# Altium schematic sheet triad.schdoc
size 594 x 419 mm; Symbol: Drawing-Symbol_A4; @Project Name: Inverted_MAML_6x6; @Page Count: 1; @Update Date: 2026-06-20; @Create Date: 2026-06-20; @Schematic Name: Schematic1; @Page No: 1; @Page Name: P1; Company: EasyEDA.com; Version: V1.0; Page Size: A4; Device: Drawing-Symbol_A4; @Create Time: 09:40:42; @Update Time: 09:40:42; Border: 1; Width: 2338; Height: 1652; Region Start: 1; X Region Count: 6; Y Region Count: 4; Blade Width: 10; Title Block Position: 3
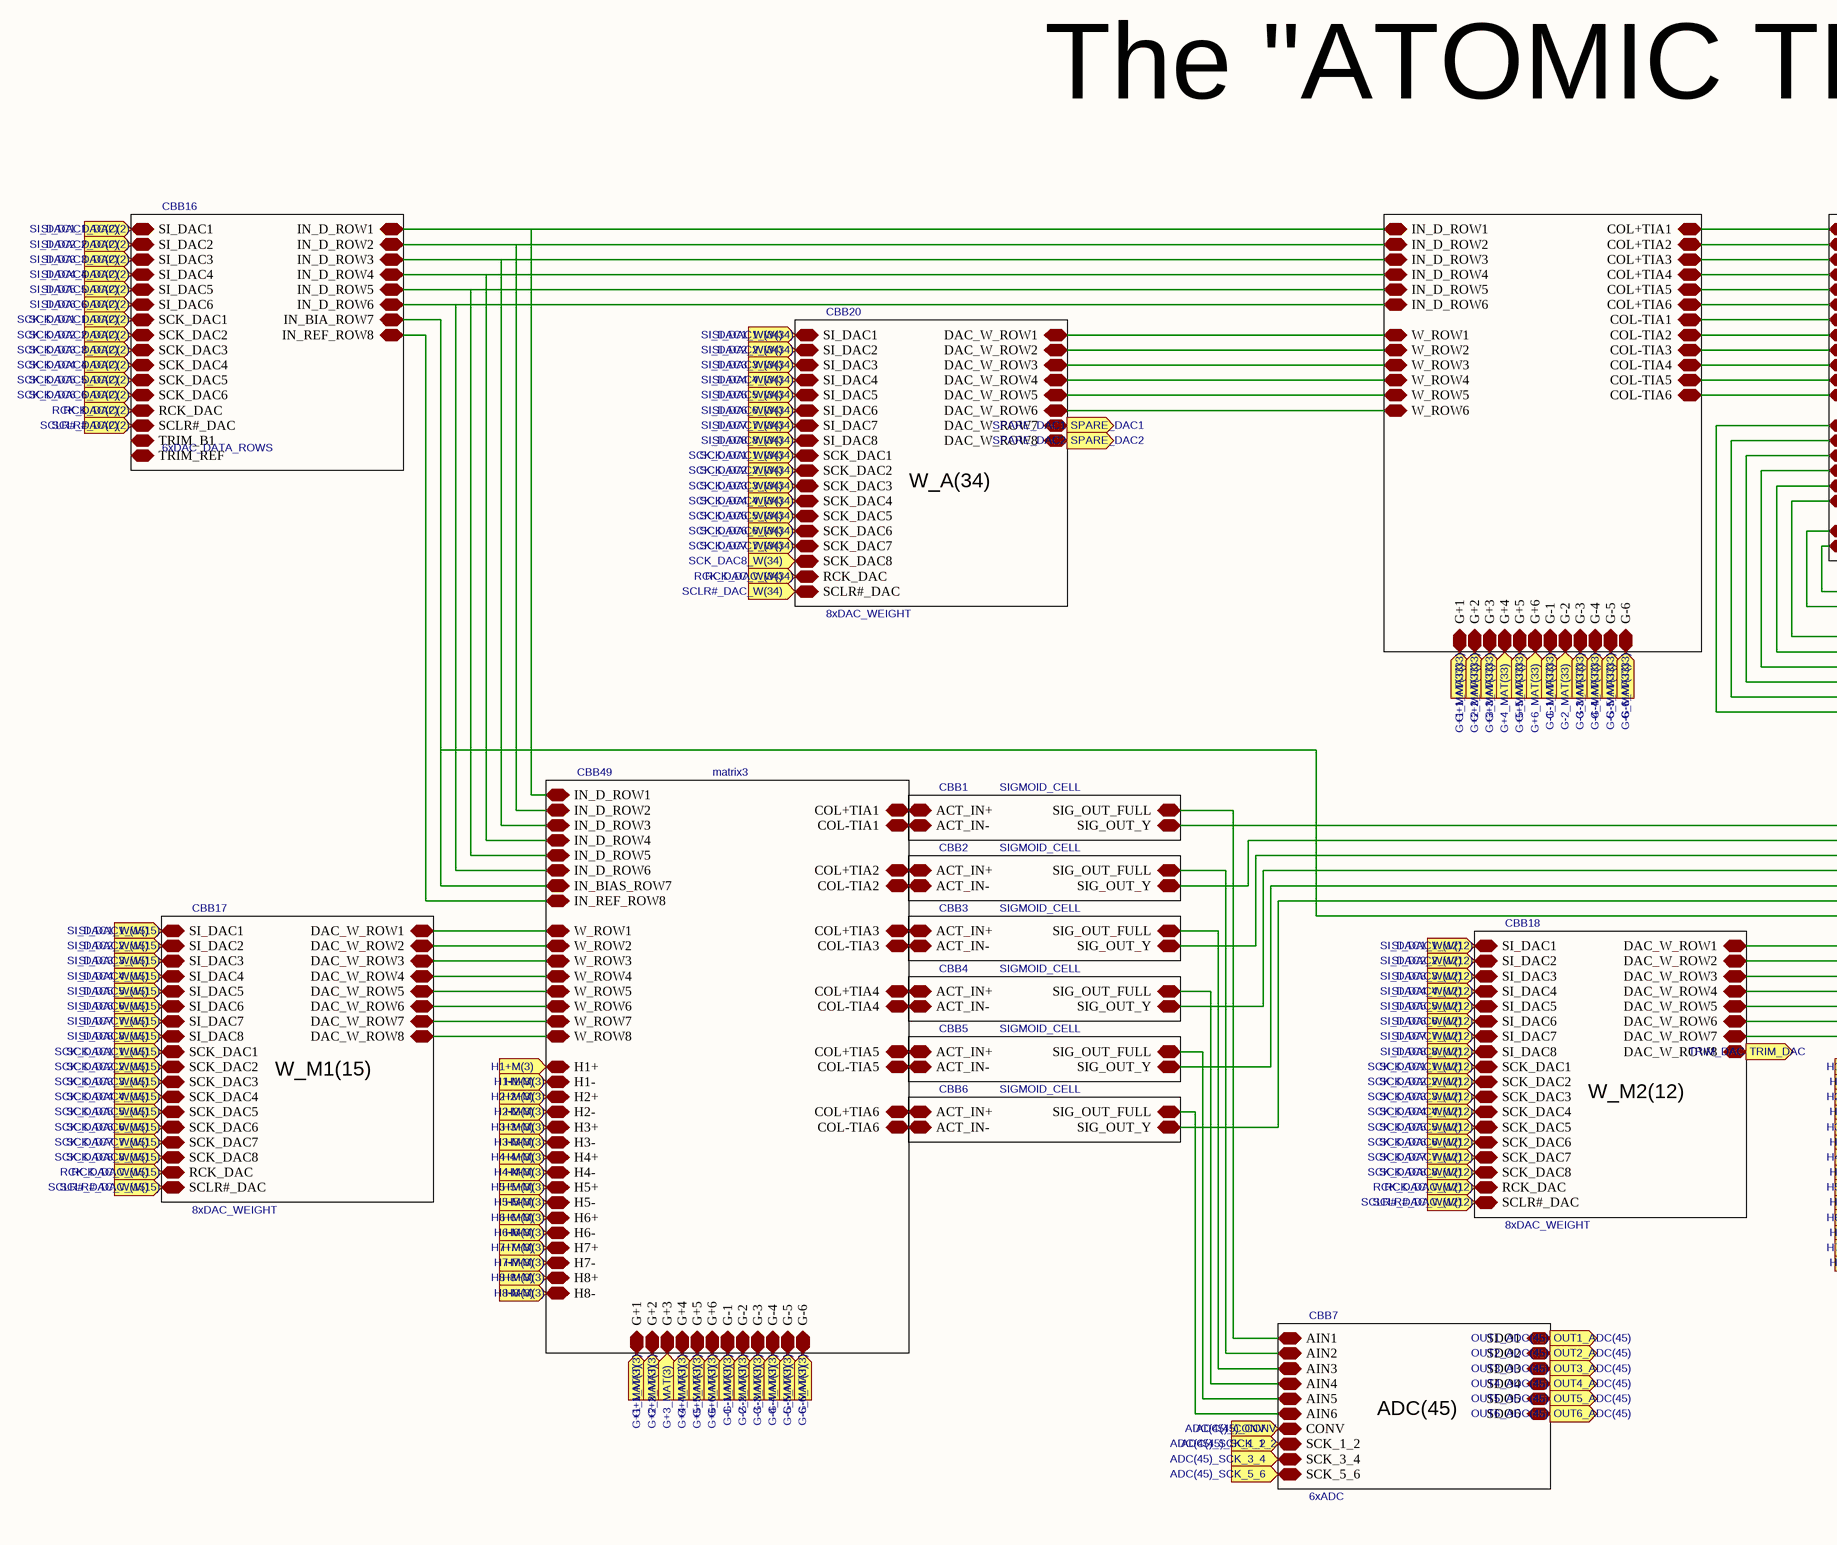
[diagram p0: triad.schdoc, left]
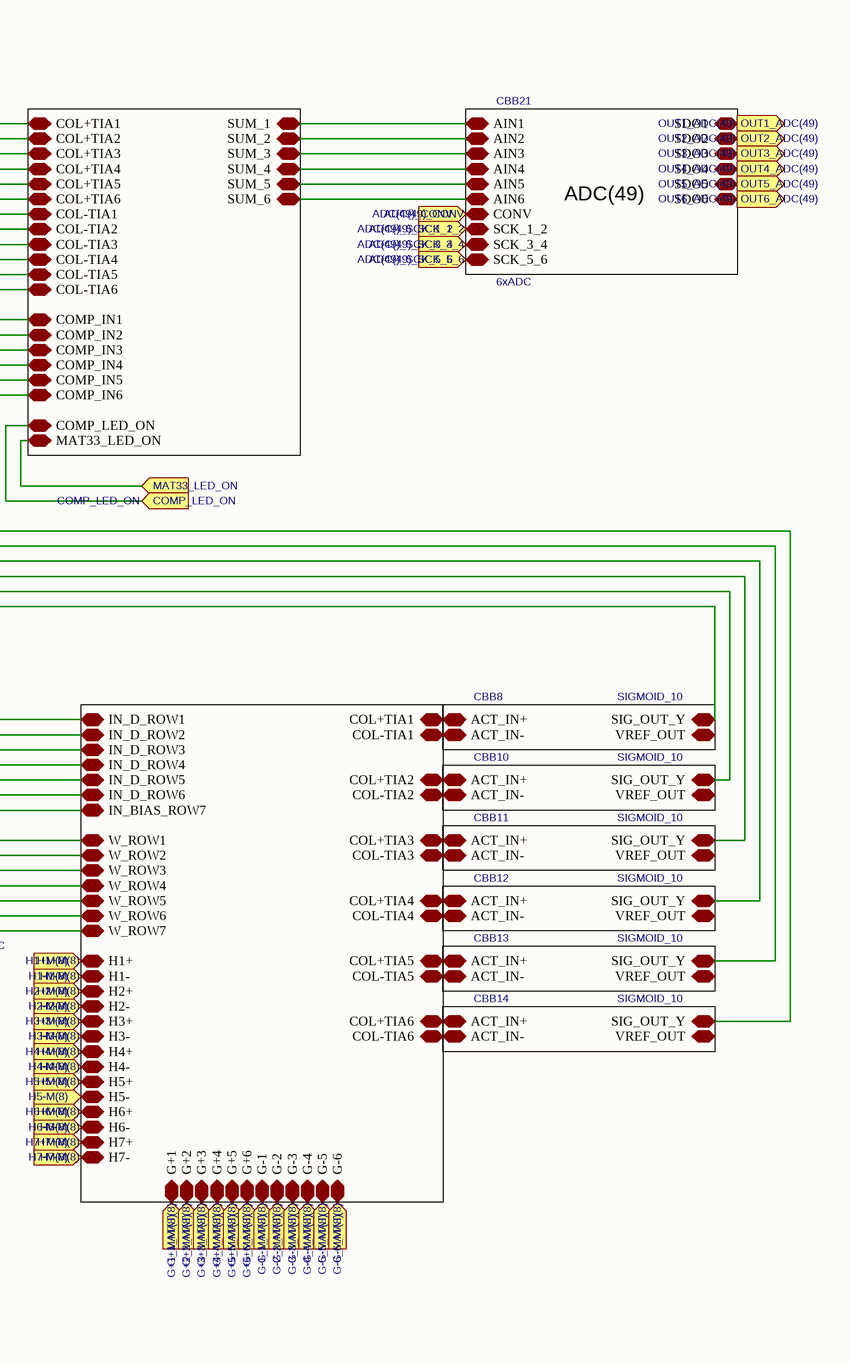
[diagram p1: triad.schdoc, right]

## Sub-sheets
CBB1 = SIMOID(4).schdoc: ACT_IN-, ACT_IN+, SIG_OUT_FULL, SIG_OUT_Y  | Symbol: SIGMOID_CELL
CBB2 = SIMOID(4).schdoc: ACT_IN-, ACT_IN+, SIG_OUT_FULL, SIG_OUT_Y  | Symbol: SIGMOID_CELL
CBB3 = SIMOID(4).schdoc: ACT_IN-, ACT_IN+, SIG_OUT_FULL, SIG_OUT_Y  | Symbol: SIGMOID_CELL
CBB4 = SIMOID(4).schdoc: ACT_IN-, ACT_IN+, SIG_OUT_FULL, SIG_OUT_Y  | Symbol: SIGMOID_CELL
CBB5 = SIMOID(4).schdoc: ACT_IN-, ACT_IN+, SIG_OUT_FULL, SIG_OUT_Y  | Symbol: SIGMOID_CELL
CBB6 = SIMOID(4).schdoc: ACT_IN-, ACT_IN+, SIG_OUT_FULL, SIG_OUT_Y  | Symbol: SIGMOID_CELL
CBB7 = ADC_BANK.schdoc: AIN1, CONV, SCK_1_2, SDO1, SDO2, SDO3, SDO4, SDO5, SDO6, AIN2, AIN3, AIN4, AIN5, AIN6, SCK_3_4, SCK_5_6  | Symbol: 6xADC
CBB8 = SIGMOID(10).schdoc: ACT_IN-, ACT_IN+, SIG_OUT_Y, VREF_OUT  | Symbol: SIGMOID_10
CBB9 = matx8.schdoc: H7+, H7-, H6-, H5-, H4-, H3-, H2-, H1-, H6+, H5+, H4+, H3+, H2+, H1+, COL-TIA6, COL-TIA5, COL-TIA4, COL-TIA3, COL-TIA2, COL-TIA1, COL+TIA6, COL+TIA5, COL+TIA4, COL+TIA3, COL+TIA2, COL+TIA1, G-6, G-5, G-4, G-3, G-2, G-1, G+6, G+5, G+4, G+3, G+2, G+1, IN_D_ROW1, IN_D_ROW2, IN_D_ROW3, IN_D_ROW4, IN_D_ROW5, IN_D_ROW6, W_ROW1, W_ROW2, W_ROW3, W_ROW4, W_ROW5, W_ROW6, W_ROW7, IN_BIAS_ROW7  | Symbol: matrix8
CBB10 = SIGMOID(10).schdoc: ACT_IN-, ACT_IN+, SIG_OUT_Y, VREF_OUT  | Symbol: SIGMOID_10
CBB11 = SIGMOID(10).schdoc: ACT_IN-, ACT_IN+, SIG_OUT_Y, VREF_OUT  | Symbol: SIGMOID_10
CBB12 = SIGMOID(10).schdoc: ACT_IN-, ACT_IN+, SIG_OUT_Y, VREF_OUT  | Symbol: SIGMOID_10
CBB13 = SIGMOID(10).schdoc: ACT_IN-, ACT_IN+, SIG_OUT_Y, VREF_OUT  | Symbol: SIGMOID_10
CBB14 = SIGMOID(10).schdoc: ACT_IN-, ACT_IN+, SIG_OUT_Y, VREF_OUT  | Symbol: SIGMOID_10
CBB15 = sum35.schdoc: COL+TIA1, COL+TIA2, COL+TIA3, COL+TIA4, COL+TIA5, COL+TIA6, COL-TIA1, COL-TIA2, COL-TIA3, COL-TIA4, COL-TIA5, COL-TIA6, COMP_IN1, COMP_IN2, COMP_IN3, COMP_IN4, COMP_IN5, COMP_IN6, SUM_1, SUM_2, SUM_3, SUM_4, SUM_5, SUM_6, COMP_LED_ON, MAT33_LED_ON  | Symbol: SUM35
CBB16 = 6xDAC_8-bit.schdoc: SI_DAC1, SI_DAC2, SI_DAC3, SI_DAC4, SI_DAC5, SI_DAC6, SCK_DAC1, SCK_DAC2, SCK_DAC3, SCK_DAC4, SCK_DAC5, SCK_DAC6, RCK_DAC, SCLR#_DAC, IN_BIA_ROW7, IN_REF_ROW8, IN_D_ROW1, IN_D_ROW2, IN_D_ROW3, IN_D_ROW4, IN_D_ROW5, IN_D_ROW6, TRIM_B1, TRIM_REF  | Symbol: 6xDAC_DATA_ROWS
CBB17 = 8xDAC_WEIGHT_8xDAC_8-bit.schdoc: SI_DAC1, SI_DAC2, SI_DAC3, SI_DAC4, SI_DAC5, SI_DAC6, SI_DAC7, SI_DAC8, SCK_DAC1, SCK_DAC2, SCK_DAC3, SCK_DAC4, SCK_DAC5, SCK_DAC6, SCK_DAC7, SCK_DAC8, RCK_DAC, SCLR#_DAC, DAC_W_ROW1, DAC_W_ROW2, DAC_W_ROW3, DAC_W_ROW4, DAC_W_ROW5, DAC_W_ROW6, DAC_W_ROW7, DAC_W_ROW8  | Symbol: 8xDAC_WEIGHT
CBB18 = 8xDAC_WEIGHT_8xDAC_8-bit.schdoc: SI_DAC1, SI_DAC2, SI_DAC3, SI_DAC4, SI_DAC5, SI_DAC6, SI_DAC7, SI_DAC8, SCK_DAC1, SCK_DAC2, SCK_DAC3, SCK_DAC4, SCK_DAC5, SCK_DAC6, SCK_DAC7, SCK_DAC8, RCK_DAC, SCLR#_DAC, DAC_W_ROW1, DAC_W_ROW2, DAC_W_ROW3, DAC_W_ROW4, DAC_W_ROW5, DAC_W_ROW6, DAC_W_ROW7, DAC_W_ROW8  | Symbol: 8xDAC_WEIGHT
CBB19 = matx33.schdoc: G+1, G+2, G+3, G+4, G+5, G+6, G-1, G-2, G-3, G-4, G-5, G-6, IN_D_ROW1, IN_D_ROW2, IN_D_ROW3, IN_D_ROW4, IN_D_ROW5, IN_D_ROW6, W_ROW1, W_ROW2, W_ROW3, W_ROW4, W_ROW5, W_ROW6, COL+TIA1, COL+TIA2, COL+TIA3, COL+TIA4, COL+TIA5, COL+TIA6, COL-TIA1, COL-TIA2, COL-TIA3, COL-TIA4, COL-TIA5, COL-TIA6  | Symbol: matrix33
CBB20 = 8xDAC_WEIGHT_8xDAC_8-bit.schdoc: SI_DAC1, SI_DAC2, SI_DAC3, SI_DAC4, SI_DAC5, SI_DAC6, SI_DAC7, SI_DAC8, SCK_DAC1, SCK_DAC2, SCK_DAC3, SCK_DAC4, SCK_DAC5, SCK_DAC6, SCK_DAC7, SCK_DAC8, RCK_DAC, SCLR#_DAC, DAC_W_ROW1, DAC_W_ROW2, DAC_W_ROW3, DAC_W_ROW4, DAC_W_ROW5, DAC_W_ROW6, DAC_W_ROW7, DAC_W_ROW8  | Symbol: 8xDAC_WEIGHT
CBB21 = ADC_BANK.schdoc: AIN1, CONV, SCK_1_2, SDO1, SDO2, SDO3, SDO4, SDO5, SDO6, AIN2, AIN3, AIN4, AIN5, AIN6, SCK_3_4, SCK_5_6  | Symbol: 6xADC
CBB49 = matx3.schdoc: G+1, G+2, G+3, G+4, G+5, G+6, G-1, G-2, G-3, G-4, G-5, G-6, COL+TIA1, COL+TIA2, COL+TIA3, COL+TIA4, COL+TIA5, COL+TIA6, COL-TIA1, COL-TIA2, COL-TIA3, COL-TIA4, COL-TIA5, COL-TIA6, H1+, H2+, H3+, H4+, H5+, H6+, H1-, H2-, H3-, H4-, H5-, H6-, H7-, H8-, H7+, H8+, W_ROW1, W_ROW2, W_ROW3, W_ROW4, W_ROW5, W_ROW6, W_ROW7, W_ROW8, IN_D_ROW1, IN_D_ROW2, IN_D_ROW3, IN_D_ROW4, IN_D_ROW5, IN_D_ROW6, IN_BIAS_ROW7, IN_REF_ROW8  | Symbol: matrix3

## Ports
ADC(45)_CONV (in), ADC(45)_SCK_1_2 (in), ADC(45)_SCK_3_4 (in), ADC(45)_SCK_5_6 (in), ADC(49)_CONV (in), ADC(49)_SCK_1_2 (in), ADC(49)_SCK_3_4 (in), ADC(49)_SCK_5_6 (in), COMP_LED_ON (in), G+1_MAT(3) (in), G+1_MAT(8) (in), G+1_MAT(33) (in), G+2_MAT(3) (in), G+2_MAT(8) (in), G+2_MAT(33) (in), G+3_MAT(3) (in), G+3_MAT(8) (in), G+3_MAT(33) (in), G+4_MAT(3) (in), G+4_MAT(8) (in), G+4_MAT(33) (in), G+5_MAT(3) (in), G+5_MAT(8) (in), G+5_MAT(33) (in), G+6_MAT(3) (in), G+6_MAT(8) (in), G+6_MAT(33) (in), G-1_MAT(3) (in), G-1_MAT(8) (in), G-1_MAT(33) (in), G-2_MAT(3) (in), G-2_MAT(8) (in), G-2_MAT(33) (in), G-3_MAT(3) (in), G-3_MAT(8) (in), G-3_MAT(33) (in), G-4_MAT(3) (in), G-4_MAT(8) (in), G-4_MAT(33) (in), G-5_MAT(3) (in), G-5_MAT(8) (in), G-5_MAT(33) (in), G-6_MAT(3) (in), G-6_MAT(8) (in), G-6_MAT(33) (in), H1+M(3) (in), H1+M(8) (in), H1-M(3) (in), H1-M(8) (in), H2+M(3) (in), H2+M(8) (in), H2-M(3) (in), H2-M(8) (in), H3+M(3) (in), H3+M(8) (in), H3-M(3) (in), H3-M(8) (in), H4+M(3) (in), H4+M(8) (in), H4-M(3) (in), H4-M(8) (in), H5+M(3) (in), H5+M(8) (in), H5-M(3) (in), H5-M(8) (in), H6+M(3) (in), H6+M(8) (in), H6-M(3) (in), H6-M(8) (in), H7+M(3) (in), H7+M(8) (in), H7-M(3) (in), H7-M(8) (in), H8+M(3) (in), H8-M(3) (in), MAT33_LED_ON (in), OUT1_ADC(45) (out), OUT1_ADC(49) (out), OUT2_ADC(45) (out), OUT2_ADC(49) (out), OUT3_ADC(45) (out), OUT3_ADC(49) (out), OUT4_ADC(45) (out), OUT4_ADC(49) (out), OUT5_ADC(45) (out), OUT5_ADC(49) (out), OUT6_ADC(45) (out), OUT6_ADC(49) (out), RCK_DAC(2) (in), RCK_DAC_W(12) (in), RCK_DAC_W(15) (in), RCK_DAC_W(34) (in), SCK_DAC1_DAC(2) (in), SCK_DAC1_W(12) (in), SCK_DAC1_W(15) (in), SCK_DAC1_W(34) (in), SCK_DAC2_DAC(2) (in), SCK_DAC2_W(12) (in), SCK_DAC2_W(15) (in), SCK_DAC2_W(34) (in), SCK_DAC3_DAC(2) (in), SCK_DAC3_W(12) (in), SCK_DAC3_W(15) (in), SCK_DAC3_W(34) (in), SCK_DAC4_DAC(2) (in), SCK_DAC4_W(12) (in), SCK_DAC4_W(15) (in), SCK_DAC4_W(34) (in), SCK_DAC5_DAC(2) (in), SCK_DAC5_W(12) (in), SCK_DAC5_W(15) (in), SCK_DAC5_W(34) (in), SCK_DAC6_DAC(2) (in), SCK_DAC6_W(12) (in), SCK_DAC6_W(15) (in), SCK_DAC6_W(34) (in), SCK_DAC7_W(12) (in), SCK_DAC7_W(15) (in), SCK_DAC7_W(34) (in), SCK_DAC8_W(12) (in), SCK_DAC8_W(15) (in), SCK_DAC8_W(34) (in), SCLR#_DAC(2) (in), SCLR#_DAC_W(12) (in), SCLR#_DAC_W(15) (in), SCLR#_DAC_W(34) (in), SI_DAC1_DAC(2) (in), SI_DAC1_W(12) (in), SI_DAC1_W(15) (in), SI_DAC1_W(34) (in), SI_DAC2_DAC(2) (in), SI_DAC2_W(12) (in), SI_DAC2_W(15) (in), SI_DAC2_W(34) (in), SI_DAC3_DAC(2) (in), SI_DAC3_W(12) (in), SI_DAC3_W(15) (in), SI_DAC3_W(34) (in), SI_DAC4_DAC(2) (in), SI_DAC4_W(12) (in), SI_DAC4_W(15) (in), SI_DAC4_W(34) (in), SI_DAC5_DAC(2) (in), SI_DAC5_W(12) (in), SI_DAC5_W(15) (in), SI_DAC5_W(34) (in), SI_DAC6_DAC(2) (in), SI_DAC6_W(12) (in), SI_DAC6_W(15) (in), SI_DAC6_W(34) (in), SI_DAC7_W(12) (in), SI_DAC7_W(15) (in), SI_DAC7_W(34) (in), SI_DAC8_W(12) (in), SI_DAC8_W(15) (in), SI_DAC8_W(34) (in), SPARE_DAC1 (out), SPARE_DAC2 (out), TRIM_DAC (out)

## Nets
ADC(45)_CONV: port ADC(45)_CONV, sheet CBB7/CONV
ADC(45)_SCK_1_2: port ADC(45)_SCK_1_2, sheet CBB7/SCK_1_2
ADC(45)_SCK_3_4: port ADC(45)_SCK_3_4, sheet CBB7/SCK_3_4
ADC(45)_SCK_5_6: port ADC(45)_SCK_5_6, sheet CBB7/SCK_5_6
ADC(49)_CONV: port ADC(49)_CONV, sheet CBB21/CONV
ADC(49)_SCK_1_2: port ADC(49)_SCK_1_2, sheet CBB21/SCK_1_2
ADC(49)_SCK_3_4: port ADC(49)_SCK_3_4, sheet CBB21/SCK_3_4
ADC(49)_SCK_5_6: port ADC(49)_SCK_5_6, sheet CBB21/SCK_5_6
COMP_LED_ON: port COMP_LED_ON, sheet CBB15/COMP_LED_ON
G+1_MAT(3): port G+1_MAT(3), sheet CBB49/G+1
G+1_MAT(8): port G+1_MAT(8), sheet CBB9/G+1
G+1_MAT(33): port G+1_MAT(33), sheet CBB19/G+1
G+2_MAT(3): port G+2_MAT(3), sheet CBB49/G+2
G+2_MAT(8): port G+2_MAT(8), sheet CBB9/G+2
G+2_MAT(33): port G+2_MAT(33), sheet CBB19/G+2
G+3_MAT(3): port G+3_MAT(3), sheet CBB49/G+3
G+3_MAT(8): port G+3_MAT(8), sheet CBB9/G+3
G+3_MAT(33): port G+3_MAT(33), sheet CBB19/G+3
G+4_MAT(3): port G+4_MAT(3), sheet CBB49/G+4
G+4_MAT(8): port G+4_MAT(8), sheet CBB9/G+4
G+4_MAT(33): port G+4_MAT(33), sheet CBB19/G+4
G+5_MAT(3): port G+5_MAT(3), sheet CBB49/G+5
G+5_MAT(8): port G+5_MAT(8), sheet CBB9/G+5
G+5_MAT(33): port G+5_MAT(33), sheet CBB19/G+5
G+6_MAT(3): port G+6_MAT(3), sheet CBB49/G+6
G+6_MAT(8): port G+6_MAT(8), sheet CBB9/G+6
G+6_MAT(33): port G+6_MAT(33), sheet CBB19/G+6
G-1_MAT(3): port G-1_MAT(3), sheet CBB49/G-1
G-1_MAT(8): port G-1_MAT(8), sheet CBB9/G-1
G-1_MAT(33): port G-1_MAT(33), sheet CBB19/G-1
G-2_MAT(3): port G-2_MAT(3), sheet CBB49/G-2
G-2_MAT(8): port G-2_MAT(8), sheet CBB9/G-2
G-2_MAT(33): port G-2_MAT(33), sheet CBB19/G-2
G-3_MAT(3): port G-3_MAT(3), sheet CBB49/G-3
G-3_MAT(8): port G-3_MAT(8), sheet CBB9/G-3
G-3_MAT(33): port G-3_MAT(33), sheet CBB19/G-3
G-4_MAT(3): port G-4_MAT(3), sheet CBB49/G-4
G-4_MAT(8): port G-4_MAT(8), sheet CBB9/G-4
G-4_MAT(33): port G-4_MAT(33), sheet CBB19/G-4
G-5_MAT(3): port G-5_MAT(3), sheet CBB49/G-5
G-5_MAT(8): port G-5_MAT(8), sheet CBB9/G-5
G-5_MAT(33): port G-5_MAT(33), sheet CBB19/G-5
G-6_MAT(3): port G-6_MAT(3), sheet CBB49/G-6
G-6_MAT(8): port G-6_MAT(8), sheet CBB9/G-6
G-6_MAT(33): port G-6_MAT(33), sheet CBB19/G-6
H1+M(3): port H1+M(3), sheet CBB49/H1+
H1+M(8): port H1+M(8), sheet CBB9/H1+
H1-M(3): port H1-M(3), sheet CBB49/H1-
H1-M(8): port H1-M(8), sheet CBB9/H1-
H2+M(3): port H2+M(3), sheet CBB49/H2+
H2+M(8): port H2+M(8), sheet CBB9/H2+
H2-M(3): port H2-M(3), sheet CBB49/H2-
H2-M(8): port H2-M(8), sheet CBB9/H2-
H3+M(3): port H3+M(3), sheet CBB49/H3+
H3+M(8): port H3+M(8), sheet CBB9/H3+
H3-M(3): port H3-M(3), sheet CBB49/H3-
H3-M(8): port H3-M(8), sheet CBB9/H3-
H4+M(3): port H4+M(3), sheet CBB49/H4+
H4+M(8): port H4+M(8), sheet CBB9/H4+
H4-M(3): port H4-M(3), sheet CBB49/H4-
H4-M(8): port H4-M(8), sheet CBB9/H4-
H5+M(3): port H5+M(3), sheet CBB49/H5+
H5+M(8): port H5+M(8), sheet CBB9/H5+
H5-M(3): port H5-M(3), sheet CBB49/H5-
H5-M(8): port H5-M(8), sheet CBB9/H5-
H6+M(3): port H6+M(3), sheet CBB49/H6+
H6+M(8): port H6+M(8), sheet CBB9/H6+
H6-M(3): port H6-M(3), sheet CBB49/H6-
H6-M(8): port H6-M(8), sheet CBB9/H6-
H7+M(3): port H7+M(3), sheet CBB49/H7+
H7+M(8): port H7+M(8), sheet CBB9/H7+
H7-M(3): port H7-M(3), sheet CBB49/H7-
H7-M(8): port H7-M(8), sheet CBB9/H7-
H8+M(3): port H8+M(3), sheet CBB49/H8+
H8-M(3): port H8-M(3), sheet CBB49/H8-
MAT33_LED_ON: port MAT33_LED_ON, sheet CBB15/MAT33_LED_ON
OUT1_ADC(45): port OUT1_ADC(45), sheet CBB7/SDO1
OUT1_ADC(49): port OUT1_ADC(49), sheet CBB21/SDO1
OUT2_ADC(45): port OUT2_ADC(45), sheet CBB7/SDO2
OUT2_ADC(49): port OUT2_ADC(49), sheet CBB21/SDO2
OUT3_ADC(45): port OUT3_ADC(45), sheet CBB7/SDO3
OUT3_ADC(49): port OUT3_ADC(49), sheet CBB21/SDO3
OUT4_ADC(45): port OUT4_ADC(45), sheet CBB7/SDO4
OUT4_ADC(49): port OUT4_ADC(49), sheet CBB21/SDO4
OUT5_ADC(45): port OUT5_ADC(45), sheet CBB7/SDO5
OUT5_ADC(49): port OUT5_ADC(49), sheet CBB21/SDO5
OUT6_ADC(45): port OUT6_ADC(45), sheet CBB7/SDO6
OUT6_ADC(49): port OUT6_ADC(49), sheet CBB21/SDO6
RCK_DAC(2): port RCK_DAC(2), sheet CBB16/RCK_DAC
RCK_DAC_W(12): port RCK_DAC_W(12), sheet CBB18/RCK_DAC
RCK_DAC_W(15): port RCK_DAC_W(15), sheet CBB17/RCK_DAC
RCK_DAC_W(34): port RCK_DAC_W(34), sheet CBB20/RCK_DAC
SCK_DAC1_DAC(2): port SCK_DAC1_DAC(2), sheet CBB16/SCK_DAC1
SCK_DAC1_W(12): port SCK_DAC1_W(12), sheet CBB18/SCK_DAC1
SCK_DAC1_W(15): port SCK_DAC1_W(15), sheet CBB17/SCK_DAC1
SCK_DAC1_W(34): port SCK_DAC1_W(34), sheet CBB20/SCK_DAC1
SCK_DAC2_DAC(2): port SCK_DAC2_DAC(2), sheet CBB16/SCK_DAC2
SCK_DAC2_W(12): port SCK_DAC2_W(12), sheet CBB18/SCK_DAC2
SCK_DAC2_W(15): port SCK_DAC2_W(15), sheet CBB17/SCK_DAC2
SCK_DAC2_W(34): port SCK_DAC2_W(34), sheet CBB20/SCK_DAC2
SCK_DAC3_DAC(2): port SCK_DAC3_DAC(2), sheet CBB16/SCK_DAC3
SCK_DAC3_W(12): port SCK_DAC3_W(12), sheet CBB18/SCK_DAC3
SCK_DAC3_W(15): port SCK_DAC3_W(15), sheet CBB17/SCK_DAC3
SCK_DAC3_W(34): port SCK_DAC3_W(34), sheet CBB20/SCK_DAC3
SCK_DAC4_DAC(2): port SCK_DAC4_DAC(2), sheet CBB16/SCK_DAC4
SCK_DAC4_W(12): port SCK_DAC4_W(12), sheet CBB18/SCK_DAC4
SCK_DAC4_W(15): port SCK_DAC4_W(15), sheet CBB17/SCK_DAC4
SCK_DAC4_W(34): port SCK_DAC4_W(34), sheet CBB20/SCK_DAC4
SCK_DAC5_DAC(2): port SCK_DAC5_DAC(2), sheet CBB16/SCK_DAC5
SCK_DAC5_W(12): port SCK_DAC5_W(12), sheet CBB18/SCK_DAC5
SCK_DAC5_W(15): port SCK_DAC5_W(15), sheet CBB17/SCK_DAC5
SCK_DAC5_W(34): port SCK_DAC5_W(34), sheet CBB20/SCK_DAC5
SCK_DAC6_DAC(2): port SCK_DAC6_DAC(2), sheet CBB16/SCK_DAC6
SCK_DAC6_W(12): port SCK_DAC6_W(12), sheet CBB18/SCK_DAC6
SCK_DAC6_W(15): port SCK_DAC6_W(15), sheet CBB17/SCK_DAC6
SCK_DAC6_W(34): port SCK_DAC6_W(34), sheet CBB20/SCK_DAC6
SCK_DAC7_W(12): port SCK_DAC7_W(12), sheet CBB18/SCK_DAC7
SCK_DAC7_W(15): port SCK_DAC7_W(15), sheet CBB17/SCK_DAC7
SCK_DAC7_W(34): port SCK_DAC7_W(34), sheet CBB20/SCK_DAC7
SCK_DAC8_W(12): port SCK_DAC8_W(12), sheet CBB18/SCK_DAC8
SCK_DAC8_W(15): port SCK_DAC8_W(15), sheet CBB17/SCK_DAC8
SCK_DAC8_W(34): port SCK_DAC8_W(34), sheet CBB20/SCK_DAC8
SCLR#_DAC(2): port SCLR#_DAC(2), sheet CBB16/SCLR#_DAC
SCLR#_DAC_W(12): port SCLR#_DAC_W(12), sheet CBB18/SCLR#_DAC
SCLR#_DAC_W(15): port SCLR#_DAC_W(15), sheet CBB17/SCLR#_DAC
SCLR#_DAC_W(34): port SCLR#_DAC_W(34), sheet CBB20/SCLR#_DAC
SI_DAC1_DAC(2): port SI_DAC1_DAC(2), sheet CBB16/SI_DAC1
SI_DAC1_W(12): port SI_DAC1_W(12), sheet CBB18/SI_DAC1
SI_DAC1_W(15): port SI_DAC1_W(15), sheet CBB17/SI_DAC1
SI_DAC1_W(34): port SI_DAC1_W(34), sheet CBB20/SI_DAC1
SI_DAC2_DAC(2): port SI_DAC2_DAC(2), sheet CBB16/SI_DAC2
SI_DAC2_W(12): port SI_DAC2_W(12), sheet CBB18/SI_DAC2
SI_DAC2_W(15): port SI_DAC2_W(15), sheet CBB17/SI_DAC2
SI_DAC2_W(34): port SI_DAC2_W(34), sheet CBB20/SI_DAC2
SI_DAC3_DAC(2): port SI_DAC3_DAC(2), sheet CBB16/SI_DAC3
SI_DAC3_W(12): port SI_DAC3_W(12), sheet CBB18/SI_DAC3
SI_DAC3_W(15): port SI_DAC3_W(15), sheet CBB17/SI_DAC3
SI_DAC3_W(34): port SI_DAC3_W(34), sheet CBB20/SI_DAC3
SI_DAC4_DAC(2): port SI_DAC4_DAC(2), sheet CBB16/SI_DAC4
SI_DAC4_W(12): port SI_DAC4_W(12), sheet CBB18/SI_DAC4
SI_DAC4_W(15): port SI_DAC4_W(15), sheet CBB17/SI_DAC4
SI_DAC4_W(34): port SI_DAC4_W(34), sheet CBB20/SI_DAC4
SI_DAC5_DAC(2): port SI_DAC5_DAC(2), sheet CBB16/SI_DAC5
SI_DAC5_W(12): port SI_DAC5_W(12), sheet CBB18/SI_DAC5
SI_DAC5_W(15): port SI_DAC5_W(15), sheet CBB17/SI_DAC5
SI_DAC5_W(34): port SI_DAC5_W(34), sheet CBB20/SI_DAC5
SI_DAC6_DAC(2): port SI_DAC6_DAC(2), sheet CBB16/SI_DAC6
SI_DAC6_W(12): port SI_DAC6_W(12), sheet CBB18/SI_DAC6
SI_DAC6_W(15): port SI_DAC6_W(15), sheet CBB17/SI_DAC6
SI_DAC6_W(34): port SI_DAC6_W(34), sheet CBB20/SI_DAC6
SI_DAC7_W(12): port SI_DAC7_W(12), sheet CBB18/SI_DAC7
SI_DAC7_W(15): port SI_DAC7_W(15), sheet CBB17/SI_DAC7
SI_DAC7_W(34): port SI_DAC7_W(34), sheet CBB20/SI_DAC7
SI_DAC8_W(12): port SI_DAC8_W(12), sheet CBB18/SI_DAC8
SI_DAC8_W(15): port SI_DAC8_W(15), sheet CBB17/SI_DAC8
SI_DAC8_W(34): port SI_DAC8_W(34), sheet CBB20/SI_DAC8
SPARE_DAC1: port SPARE_DAC1, sheet CBB20/DAC_W_ROW7
SPARE_DAC2: port SPARE_DAC2, sheet CBB20/DAC_W_ROW8
TRIM_DAC: port TRIM_DAC, sheet CBB18/DAC_W_ROW8
(unnamed): sheet CBB49/COL+TIA1, sheet CBB1/ACT_IN+
(unnamed): sheet CBB49/COL+TIA2, sheet CBB2/ACT_IN+  [a separate net that carries the same name]
(unnamed): sheet CBB49/COL+TIA3, sheet CBB3/ACT_IN+  [a separate net that carries the same name]
(unnamed): sheet CBB49/COL+TIA4, sheet CBB4/ACT_IN+  [a separate net that carries the same name]
(unnamed): sheet CBB49/COL+TIA5, sheet CBB5/ACT_IN+  [a separate net that carries the same name]
(unnamed): sheet CBB49/COL+TIA6, sheet CBB6/ACT_IN+  [a separate net that carries the same name]
(unnamed): sheet CBB49/COL-TIA1, sheet CBB1/ACT_IN-  [a separate net that carries the same name]
(unnamed): sheet CBB49/COL-TIA2, sheet CBB2/ACT_IN-  [a separate net that carries the same name]
(unnamed): sheet CBB49/COL-TIA3, sheet CBB3/ACT_IN-  [a separate net that carries the same name]
(unnamed): sheet CBB49/COL-TIA4, sheet CBB4/ACT_IN-  [a separate net that carries the same name]
(unnamed): sheet CBB49/COL-TIA5, sheet CBB5/ACT_IN-  [a separate net that carries the same name]
(unnamed): sheet CBB49/COL-TIA6, sheet CBB6/ACT_IN-  [a separate net that carries the same name]
(unnamed): sheet CBB49/W_ROW1, sheet CBB17/DAC_W_ROW1  [a separate net that carries the same name]
(unnamed): sheet CBB49/W_ROW2, sheet CBB17/DAC_W_ROW2  [a separate net that carries the same name]
(unnamed): sheet CBB49/W_ROW3, sheet CBB17/DAC_W_ROW3  [a separate net that carries the same name]
(unnamed): sheet CBB49/W_ROW4, sheet CBB17/DAC_W_ROW4  [a separate net that carries the same name]
(unnamed): sheet CBB49/W_ROW5, sheet CBB17/DAC_W_ROW5  [a separate net that carries the same name]
(unnamed): sheet CBB49/W_ROW6, sheet CBB17/DAC_W_ROW6  [a separate net that carries the same name]
(unnamed): sheet CBB49/W_ROW7, sheet CBB17/DAC_W_ROW7  [a separate net that carries the same name]
(unnamed): sheet CBB49/W_ROW8, sheet CBB17/DAC_W_ROW8  [a separate net that carries the same name]
(unnamed): sheet CBB49/IN_D_ROW1, sheet CBB16/IN_D_ROW1, sheet CBB19/IN_D_ROW1  [a separate net that carries the same name]
(unnamed): sheet CBB49/IN_D_ROW2, sheet CBB16/IN_D_ROW2, sheet CBB19/IN_D_ROW2  [a separate net that carries the same name]
(unnamed): sheet CBB49/IN_D_ROW3, sheet CBB16/IN_D_ROW3, sheet CBB19/IN_D_ROW3  [a separate net that carries the same name]
(unnamed): sheet CBB49/IN_D_ROW4, sheet CBB16/IN_D_ROW4, sheet CBB19/IN_D_ROW4  [a separate net that carries the same name]
(unnamed): sheet CBB49/IN_D_ROW5, sheet CBB16/IN_D_ROW5, sheet CBB19/IN_D_ROW5  [a separate net that carries the same name]
(unnamed): sheet CBB49/IN_D_ROW6, sheet CBB16/IN_D_ROW6, sheet CBB19/IN_D_ROW6  [a separate net that carries the same name]
(unnamed): sheet CBB49/IN_BIAS_ROW7, sheet CBB9/IN_BIAS_ROW7, sheet CBB16/IN_BIA_ROW7  [a separate net that carries the same name]
(unnamed): sheet CBB49/IN_REF_ROW8, sheet CBB16/IN_REF_ROW8  [a separate net that carries the same name]
(unnamed): sheet CBB1/SIG_OUT_FULL, sheet CBB7/AIN1  [a separate net that carries the same name]
(unnamed): sheet CBB1/SIG_OUT_Y, sheet CBB9/IN_D_ROW1  [a separate net that carries the same name]
(unnamed): sheet CBB2/SIG_OUT_FULL, sheet CBB7/AIN2  [a separate net that carries the same name]
(unnamed): sheet CBB2/SIG_OUT_Y, sheet CBB9/IN_D_ROW2  [a separate net that carries the same name]
(unnamed): sheet CBB3/SIG_OUT_FULL, sheet CBB7/AIN3  [a separate net that carries the same name]
(unnamed): sheet CBB3/SIG_OUT_Y, sheet CBB9/IN_D_ROW3  [a separate net that carries the same name]
(unnamed): sheet CBB4/SIG_OUT_FULL, sheet CBB7/AIN4  [a separate net that carries the same name]
(unnamed): sheet CBB4/SIG_OUT_Y, sheet CBB9/IN_D_ROW4  [a separate net that carries the same name]
(unnamed): sheet CBB5/SIG_OUT_FULL, sheet CBB7/AIN5  [a separate net that carries the same name]
(unnamed): sheet CBB5/SIG_OUT_Y, sheet CBB9/IN_D_ROW5  [a separate net that carries the same name]
(unnamed): sheet CBB6/SIG_OUT_FULL, sheet CBB7/AIN6  [a separate net that carries the same name]
(unnamed): sheet CBB6/SIG_OUT_Y, sheet CBB9/IN_D_ROW6  [a separate net that carries the same name]
(unnamed): sheet CBB21/AIN1, sheet CBB15/SUM_1  [a separate net that carries the same name]
(unnamed): sheet CBB21/AIN2, sheet CBB15/SUM_2  [a separate net that carries the same name]
(unnamed): sheet CBB21/AIN3, sheet CBB15/SUM_3  [a separate net that carries the same name]
(unnamed): sheet CBB21/AIN4, sheet CBB15/SUM_4  [a separate net that carries the same name]
(unnamed): sheet CBB21/AIN5, sheet CBB15/SUM_5  [a separate net that carries the same name]
(unnamed): sheet CBB21/AIN6, sheet CBB15/SUM_6  [a separate net that carries the same name]
(unnamed): sheet CBB8/ACT_IN-, sheet CBB9/COL-TIA1  [a separate net that carries the same name]
(unnamed): sheet CBB8/ACT_IN+, sheet CBB9/COL+TIA1  [a separate net that carries the same name]
(unnamed): sheet CBB8/SIG_OUT_Y, sheet CBB15/COMP_IN1  [a separate net that carries the same name]
(unnamed): sheet CBB10/ACT_IN-, sheet CBB9/COL-TIA2  [a separate net that carries the same name]
(unnamed): sheet CBB10/ACT_IN+, sheet CBB9/COL+TIA2  [a separate net that carries the same name]
(unnamed): sheet CBB10/SIG_OUT_Y, sheet CBB15/COMP_IN2  [a separate net that carries the same name]
(unnamed): sheet CBB11/ACT_IN-, sheet CBB9/COL-TIA3  [a separate net that carries the same name]
(unnamed): sheet CBB11/ACT_IN+, sheet CBB9/COL+TIA3  [a separate net that carries the same name]
(unnamed): sheet CBB11/SIG_OUT_Y, sheet CBB15/COMP_IN3  [a separate net that carries the same name]
(unnamed): sheet CBB12/ACT_IN-, sheet CBB9/COL-TIA4  [a separate net that carries the same name]
(unnamed): sheet CBB12/ACT_IN+, sheet CBB9/COL+TIA4  [a separate net that carries the same name]
(unnamed): sheet CBB12/SIG_OUT_Y, sheet CBB15/COMP_IN4  [a separate net that carries the same name]
(unnamed): sheet CBB13/ACT_IN-, sheet CBB9/COL-TIA5  [a separate net that carries the same name]
(unnamed): sheet CBB13/ACT_IN+, sheet CBB9/COL+TIA5  [a separate net that carries the same name]
(unnamed): sheet CBB13/SIG_OUT_Y, sheet CBB15/COMP_IN5  [a separate net that carries the same name]
(unnamed): sheet CBB14/ACT_IN-, sheet CBB9/COL-TIA6  [a separate net that carries the same name]
(unnamed): sheet CBB14/ACT_IN+, sheet CBB9/COL+TIA6  [a separate net that carries the same name]
(unnamed): sheet CBB14/SIG_OUT_Y, sheet CBB15/COMP_IN6  [a separate net that carries the same name]
(unnamed): sheet CBB9/W_ROW1, sheet CBB18/DAC_W_ROW1  [a separate net that carries the same name]
(unnamed): sheet CBB9/W_ROW2, sheet CBB18/DAC_W_ROW2  [a separate net that carries the same name]
(unnamed): sheet CBB9/W_ROW3, sheet CBB18/DAC_W_ROW3  [a separate net that carries the same name]
(unnamed): sheet CBB9/W_ROW4, sheet CBB18/DAC_W_ROW4  [a separate net that carries the same name]
(unnamed): sheet CBB9/W_ROW5, sheet CBB18/DAC_W_ROW5  [a separate net that carries the same name]
(unnamed): sheet CBB9/W_ROW6, sheet CBB18/DAC_W_ROW6  [a separate net that carries the same name]
(unnamed): sheet CBB9/W_ROW7, sheet CBB18/DAC_W_ROW7  [a separate net that carries the same name]
(unnamed): sheet CBB20/DAC_W_ROW1, sheet CBB19/W_ROW1  [a separate net that carries the same name]
(unnamed): sheet CBB20/DAC_W_ROW2, sheet CBB19/W_ROW2  [a separate net that carries the same name]
(unnamed): sheet CBB20/DAC_W_ROW3, sheet CBB19/W_ROW3  [a separate net that carries the same name]
(unnamed): sheet CBB20/DAC_W_ROW4, sheet CBB19/W_ROW4  [a separate net that carries the same name]
(unnamed): sheet CBB20/DAC_W_ROW5, sheet CBB19/W_ROW5  [a separate net that carries the same name]
(unnamed): sheet CBB20/DAC_W_ROW6, sheet CBB19/W_ROW6  [a separate net that carries the same name]
(unnamed): sheet CBB19/COL+TIA1, sheet CBB15/COL+TIA1  [a separate net that carries the same name]
(unnamed): sheet CBB19/COL+TIA2, sheet CBB15/COL+TIA2  [a separate net that carries the same name]
(unnamed): sheet CBB19/COL+TIA3, sheet CBB15/COL+TIA3  [a separate net that carries the same name]
(unnamed): sheet CBB19/COL+TIA4, sheet CBB15/COL+TIA4  [a separate net that carries the same name]
(unnamed): sheet CBB19/COL+TIA5, sheet CBB15/COL+TIA5  [a separate net that carries the same name]
(unnamed): sheet CBB19/COL+TIA6, sheet CBB15/COL+TIA6  [a separate net that carries the same name]
(unnamed): sheet CBB19/COL-TIA1, sheet CBB15/COL-TIA1  [a separate net that carries the same name]
(unnamed): sheet CBB19/COL-TIA2, sheet CBB15/COL-TIA2  [a separate net that carries the same name]
(unnamed): sheet CBB19/COL-TIA3, sheet CBB15/COL-TIA3  [a separate net that carries the same name]
(unnamed): sheet CBB19/COL-TIA4, sheet CBB15/COL-TIA4  [a separate net that carries the same name]
(unnamed): sheet CBB19/COL-TIA5, sheet CBB15/COL-TIA5  [a separate net that carries the same name]
(unnamed): sheet CBB19/COL-TIA6, sheet CBB15/COL-TIA6  [a separate net that carries the same name]

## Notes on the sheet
- The "ATOMIC TRIAD"
- ADC(49)
- W_A(34)
- W_M1(15)
- W_M2(12)
- ADC(45)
